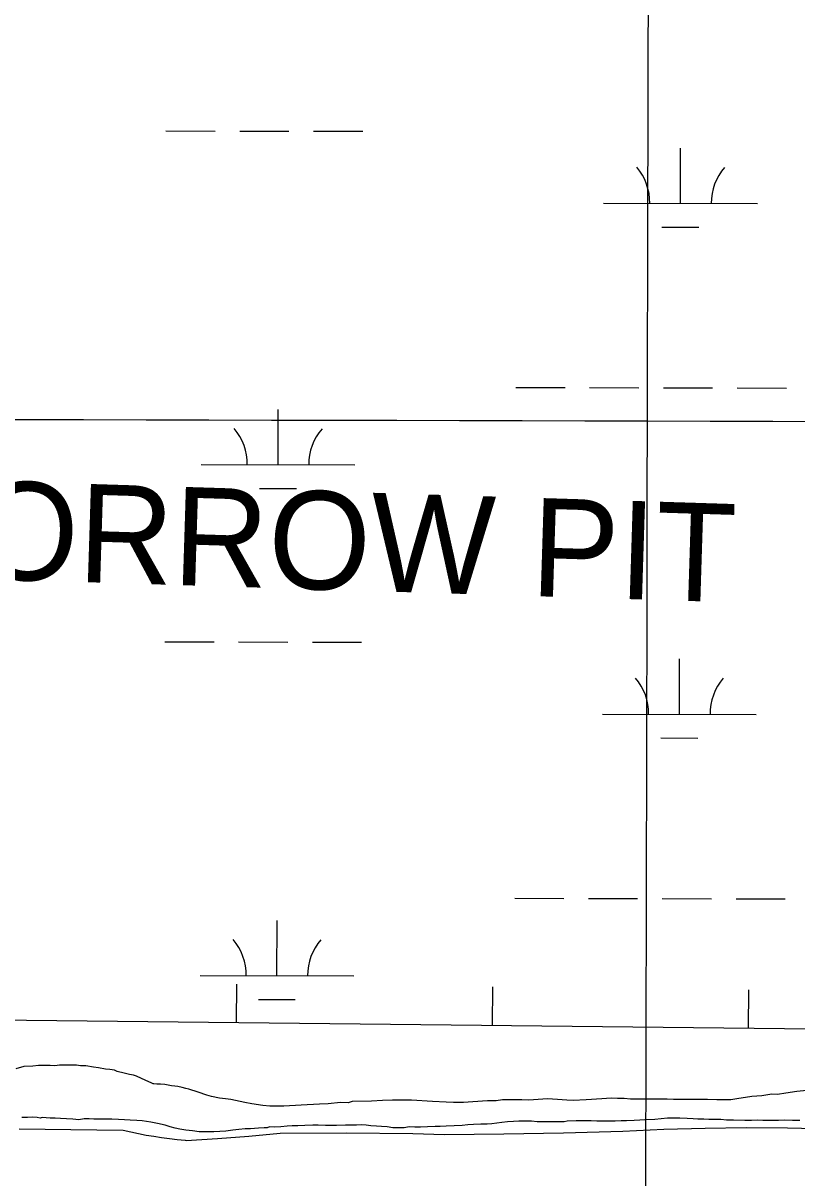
# Model space of a CAD drawing. Extents: x 3180038 to 3217926, y 922069 to 947485.
# Drawn here: x 3191717 to 3192221, y 939132 to 939884 of the extents above; entities that cross this region are included whole.
import ezdxf

# ---------------------------------------------------------------- set-up
doc = ezdxf.new("R2010")
doc.units = 0
for name, color, linetype in [('V-BORW-IDEN', 7, 'Continuous'), ('V-BORW-LINE', 7, 'Continuous'), ('V-GRID-MAJR', 7, 'Continuous'), ('V-LEVE-TOET', 7, 'Continuous'), ('V-SITE-VEGE', 7, 'Continuous'), ('V-WETL-SWMP', 7, 'Continuous')]:
    doc.layers.add(name, color=color, linetype=linetype)

msp = doc.modelspace()

# ---------------------------------------------------------------- linework, layer by layer
at = {"layer": 'V-BORW-LINE'}
for p, q in [((3191856.19, 939232.9), (3191856.46, 939257.89)), ((3192022.78, 939231.05), (3192023.06, 939256.05)), ((3192189.37, 939229.21), (3192189.65, 939254.21))]:
    msp.add_line(p, q, dxfattribs=at)
msp.add_lwpolyline([(3191226.25, 939239.86), (3192291.67, 939228.08)], dxfattribs=at)
at = {"layer": 'V-GRID-MAJR'}
for points in [[(3192093.67, 927501.08), (3192108.66, 933561.54), (3192123.65, 939624.61), (3192138.64, 945687.73), (3192138.65, 945690.29)], [(3184296.34, 939644.82), (3186905.45, 939637.89), (3192123.65, 939624.61), (3197341.86, 939612.09), (3202560.07, 939600.32), (3207778.28, 939589.32), (3212996.49, 939579.07), (3215605.59, 939574.23)]]:
    msp.add_spline(points, degree=3, dxfattribs=at)
at = {"layer": 'V-LEVE-TOET'}
for points in [[(3191714.79, 939163.6), (3191765.5, 939163.14), (3191782.49, 939162.79), (3191782.49, 939162.79), (3191787.47, 939161.67), (3191792.47, 939160.63), (3191797.49, 939159.68), (3191802.52, 939158.82), (3191807.57, 939158.05), (3191812.63, 939157.36), (3191817.7, 939156.77), (3191822.79, 939156.26), (3191823.57, 939156.19), (3191823.57, 939156.19), (3191843.99, 939157.39), (3191864.38, 939158.95), (3191884.74, 939160.86), (3191884.74, 939160.86), (3191927.88, 939161.08), (3191971.01, 939160.55), (3191991.58, 939160.03), (3191991.58, 939160.03), (3192030.25, 939160.42), (3192068.92, 939161.16), (3192107.57, 939162.27)], [(3192107.57, 939162.27), (3192134.33, 939163.47), (3192161.11, 939164.21), (3192187.9, 939164.48), (3192214.69, 939164.28), (3192233, 939163.87)]]:
    msp.add_lwpolyline(points, dxfattribs=at)
at = {"layer": 'V-SITE-VEGE'}
for points in [[(3192172.57, 939182.63), (3192168.77, 939182.66), (3192162.7, 939182.71), (3192149.79, 939182.81), (3192147.51, 939182.82), (3192140.68, 939182.88), (3192136.5, 939182.91), (3192131.19, 939182.95), (3192122.46, 939183.02), (3192112.59, 939183.09), (3192108.42, 939183.51), (3192104.24, 939183.54), (3192100.06, 939183.57), (3192093.99, 939183.24), (3192083.73, 939182.56), (3192075.38, 939182.24), (3192071.2, 939182.28), (3192065.13, 939182.7), (3192058.68, 939183.13), (3192046.53, 939182.47), (3192041.97, 939182.5), (3192037.04, 939182.54), (3192029.44, 939182.6), (3192025.26, 939181.87), (3192019.57, 939181.91), (3192010.07, 939181.23), (3192003.99, 939180.9), (3191997.54, 939180.95), (3191992.6, 939180.99), (3191983.88, 939181.43), (3191970.22, 939182.3), (3191962.62, 939182.36), (3191957.69, 939182.39), (3191951.23, 939182.06), (3191944.02, 939181.74), (3191931.49, 939181.46), (3191928.82, 939180.72), (3191923.89, 939180.76), (3191915.91, 939180.06), (3191910.21, 939179.73), (3191898.44, 939179.06), (3191887.04, 939178.39), (3191880.21, 939178.44), (3191877.93, 939178.46), (3191873.38, 939178.87), (3191866.18, 939180.07), (3191861.63, 939180.86), (3191852.53, 939182.83), (3191849.12, 939183.24), (3191845.32, 939183.64), (3191840.02, 939184.83), (3191836.99, 939185.61), (3191831.31, 939187.55), (3191825.25, 939189.49), (3191823.23, 939189.89), (3191820.83, 939190.54), (3191818.17, 939191.19), (3191816.15, 939191.46), (3191814, 939191.73), (3191809.71, 939192.53), (3191806.92, 939192.68), (3191804.52, 939192.82), (3191802.5, 939192.96), (3191802.12, 939192.96), (3191800.69, 939193.69), (3191797.28, 939195.24), (3191791.23, 939197.94), (3191789.34, 939198.71), (3191786.68, 939199.12), (3191783.27, 939199.9), (3191778.73, 939201.07), (3191776.84, 939201.85), (3191773.8, 939202.25), (3191771.15, 939202.65), (3191766.6, 939203.45), (3191763.18, 939203.85), (3191758.25, 939204.65), (3191754.84, 939204.68), (3191752.18, 939205.08), (3191746.87, 939205.12), (3191741.17, 939205.16), (3191738.13, 939204.81), (3191735.1, 939204.83), (3191732.06, 939204.85), (3191727.5, 939204.89), (3191723.71, 939204.54), (3191718.01, 939204.2), (3191712.68, 939202.72)], [(3192227.28, 939188.66), (3192220.83, 939187.95), (3192213.6, 939186.87), (3192208.28, 939186.15), (3192204.49, 939186.18), (3192198.02, 939185.09), (3192191.57, 939184.76), (3192181.69, 939183.32), (3192177.88, 939182.59), (3192172.57, 939182.63)]]:
    msp.add_lwpolyline(points, dxfattribs=at)
at = {"layer": 'V-WETL-SWMP'}
for p, q in [((3191810.4, 939813.48), (3191842.4, 939813.4)), ((3191858.4, 939813.37), (3191890.4, 939813.3)), ((3191906.4, 939813.26), (3191938.4, 939813.19)), ((3192145.13, 939766.29), (3192145.22, 939802.29)), ((3192095.13, 939766.4), (3192195.13, 939766.18)), ((3192133.1, 939750.89), (3192157.1, 939750.83)), ((3192038.02, 939646.46), (3192070.02, 939646.39)), ((3192086.02, 939646.35), (3192118.02, 939646.28)), ((3192134.02, 939646.25), (3192166.02, 939646.17)), ((3192182.02, 939646.14), (3192214.02, 939646.06)), ((3191883.31, 939596.07), (3191883.4, 939632.07)), ((3191833.31, 939596.18), (3191933.31, 939595.96)), ((3191871.28, 939580.66), (3191895.28, 939580.61)), ((3191809.65, 939480.8), (3191841.65, 939480.73)), ((3191857.65, 939480.69), (3191889.65, 939480.62)), ((3191905.65, 939480.59), (3191937.65, 939480.51)), ((3192144.38, 939433.62), (3192144.47, 939469.62)), ((3192094.38, 939433.73), (3192194.38, 939433.5)), ((3192132.35, 939418.21), (3192156.35, 939418.16)), ((3192037.27, 939313.79), (3192069.27, 939313.72)), ((3192085.27, 939313.68), (3192117.27, 939313.61)), ((3192133.27, 939313.57), (3192165.27, 939313.5)), ((3192181.27, 939313.46), (3192213.27, 939313.39)), ((3191882.56, 939263.39), (3191882.65, 939299.39)), ((3191832.56, 939263.51), (3191932.56, 939263.28)), ((3191870.53, 939247.99), (3191894.53, 939247.94))]:
    msp.add_line(p, q, dxfattribs=at)
for points in [[(3192077.26, 939168.9), (3192071.35, 939168.59), (3192069.56, 939168.24), (3192068.31, 939168.25), (3192064.91, 939168.28), (3192061.51, 939168.3), (3192057.75, 939168.33), (3192051.85, 939168.2), (3192048.1, 939168.59), (3192043.09, 939168.63), (3192040.05, 939168.65), (3192036.47, 939168.5), (3192032.53, 939168.17), (3192028.95, 939167.84), (3192025.55, 939167.33), (3192022.5, 939167), (3192019.28, 939166.84), (3192015.34, 939166.69), (3192010.51, 939166.55), (3192006.75, 939166.22), (3192003.17, 939165.89), (3191997.98, 939165.58), (3191992.79, 939165.44), (3191988.86, 939165.29), (3191985.46, 939165.14), (3191980.63, 939164.99), (3191975.97, 939164.85), (3191972.22, 939164.88), (3191968.64, 939164.91), (3191965.42, 939164.4), (3191961.12, 939164.25), (3191958.08, 939164.45), (3191954.33, 939165.02), (3191950.58, 939165.23), (3191947.36, 939165.43), (3191943.78, 939165.64), (3191940.74, 939166.02), (3191937.7, 939166.22), (3191934.3, 939166.07), (3191930.37, 939166.1), (3191927.15, 939166.12), (3191921.42, 939165.81), (3191917.84, 939165.84), (3191914.27, 939165.87), (3191909.44, 939166.08), (3191905.86, 939166.11), (3191900.67, 939165.79), (3191896.2, 939165.65), (3191892.44, 939165.68), (3191889.22, 939165.34), (3191885.1, 939165.02), (3191881.16, 939164.87), (3191877.77, 939164.9), (3191876.33, 939164.37), (3191874.36, 939164.39), (3191870.6, 939164.06), (3191865.41, 939163.74), (3191862.02, 939163.77), (3191857.72, 939163.26), (3191853.96, 939162.76), (3191849.3, 939162.25), (3191845.36, 939161.93), (3191841.61, 939161.78), (3191838.39, 939161.8), (3191834.99, 939161.83), (3191831.95, 939161.85), (3191827.66, 939162.42), (3191823.37, 939162.81), (3191819.44, 939163.56), (3191816.4, 939164.12), (3191813.19, 939165.04), (3191809.8, 939166.14), (3191804.98, 939167.25), (3191800.51, 939168), (3191794.97, 939168.94), (3191791.4, 939169.14), (3191787.1, 939169.35), (3191783.35, 939169.56), (3191779.42, 939169.77), (3191775.12, 939169.98), (3191769.94, 939170.02), (3191766.9, 939170.05), (3191763.5, 939170.07), (3191760.46, 939170.1), (3191757.24, 939170.12), (3191753.65, 939169.61), (3191749.9, 939170), (3191745.61, 939170.21), (3191741.85, 939170.42), (3191738.28, 939170.63), (3191735.06, 939170.65), (3191729.87, 939171.05), (3191728.62, 939170.7), (3191726.65, 939171.08), (3191723.44, 939171.28), (3191720.21, 939171.12), (3191716.64, 939171.15)], [(3192222.69, 939169.02), (3192218.04, 939169.06), (3192212.86, 939169.28), (3192208.92, 939169.13), (3192205.52, 939169.16), (3192201.94, 939169.18), (3192198.72, 939169.21), (3192195.15, 939169.24), (3192191.39, 939169.09), (3192186.92, 939169.12), (3192179.58, 939169.36), (3192175.11, 939169.39), (3192171.36, 939169.78), (3192167.07, 939169.81), (3192163.67, 939169.84), (3192160.27, 939170.04), (3192156.51, 939170.07), (3192153.47, 939170.1), (3192149.54, 939170.48), (3192144.71, 939170.7), (3192140.6, 939170.73), (3192136.66, 939170.58), (3192132.54, 939170.26), (3192128.43, 939169.75), (3192121.98, 939169.45), (3192118.76, 939169.29), (3192115, 939169.14), (3192109.99, 939169), (3192106.59, 939168.85), (3192102.66, 939168.7), (3192097.83, 939168.74), (3192094.79, 939168.76), (3192090.67, 939168.79), (3192086.92, 939168.82), (3192083.88, 939168.85), (3192080.3, 939168.87), (3192077.26, 939168.9)]]:
    msp.add_lwpolyline(points, dxfattribs=at)
for centre, start, end in [((3192089.89, 939766.89), 359.09901, 40.64267), ((3192200.38, 939766.64), 139.09901, 180.64267), ((3191828.07, 939596.67), 359.09901, 40.64267), ((3191938.56, 939596.42), 139.09901, 180.64267), ((3192089.14, 939434.22), 359.09901, 40.64267), ((3192199.63, 939433.97), 139.09901, 180.64267), ((3191827.32, 939263.99), 359.09901, 40.64267), ((3191937.81, 939263.74), 139.09901, 180.64267)]:
    msp.add_arc(centre, 35.25, start, end, dxfattribs=at)

# ---------------------------------------------------------------- texts
at = {"layer": 'V-BORW-IDEN'}
msp.add_text('BORROW PIT', height=64, rotation=358.21326, dxfattribs=at).set_placement((3191628.98, 939523.67))

doc.saveas('drawing.dxf')
